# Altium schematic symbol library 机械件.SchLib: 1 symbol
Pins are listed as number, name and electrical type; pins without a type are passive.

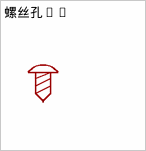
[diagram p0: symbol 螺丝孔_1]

## 螺丝孔_1
designator *?  (value not drawn)
footprint M3螺丝
pins: 1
